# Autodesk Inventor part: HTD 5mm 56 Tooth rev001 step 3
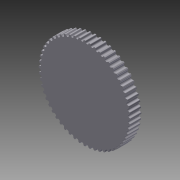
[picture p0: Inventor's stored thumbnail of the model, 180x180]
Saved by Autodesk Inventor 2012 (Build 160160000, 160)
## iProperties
Created: 2011-12
Part Number: HTD 5mm 56 Tooth rev001 step 3
Document SubType Name: Modeling
Designer: Alex
Density: 2.71 g/cm^3
Material: Aluminum-6061
Author: Alex
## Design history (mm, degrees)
sketch "Sketch2"
  geometry: C1 r 43.993 at (0, 0); 1 further point
  constraints: 1 centre point, 1 coincident
  dimensions: "d197" = 87.9856 diameter of C1
extrude "Extrusion1" new body sketch "Sketch2" distance "d198" = 10.5664; taper "d199" = 0 deg
sketch "Sketch1"
  geometry: L1 (0, 0)-(0, 28.7); L2 (-28.232, 0)-(27.326, 0); L3 (1.426, 25.389)-(0, 0); L4 (-1.426, 25.389)-(0, 0); L5 (2.201, 41.903)-(2.505, 41.886); L6 (0.897, 43.637)-(1.14, 42.758); L7 (3.994, 43.463)-(3.655, 42.617); L8 (-43.954, 44.031)-(44.031, 43.954); L9 (44.031, 43.954)-(43.954, -44.031); L10 (43.954, -44.031)-(-44.031, -43.954); L11 (-44.031, -43.954)-(-43.954, 44.031); L12 (-0.897, 43.637)-(-1.14, 42.758); L13 (-2.505, 41.886)-(-2.201, 41.903); L14 (-3.994, 43.463)-(-3.655, 42.617); L15 (-5.777, 43.262)-(-5.92, 42.362); L16 (-7.179, 41.342)-(-6.878, 41.393); L17 (-8.836, 42.742)-(-8.403, 41.94); L18 (-10.585, 42.343)-(-10.626, 41.433); L19 (-11.763, 40.279)-(-11.47, 40.363); L20 (-13.566, 41.484)-(-13.046, 40.735); L21 (-15.259, 40.892)-(-15.198, 39.982); L22 (-16.199, 38.708)-(-15.917, 38.825); L23 (-18.125, 39.705)-(-17.525, 39.019); L24 (-19.741, 38.926)-(-19.579, 38.029); L25 (-20.431, 36.651)-(-20.164, 36.799); L26 (-22.457, 37.426)-(-21.783, 36.811); L27 (-23.976, 36.471)-(-23.714, 35.598); L28 (-24.406, 34.133)-(-24.157, 34.31); L29 (-26.506, 34.676)-(-25.768, 34.141); L30 (-27.908, 33.557)-(-27.551, 32.719); L31 (-28.074, 31.186)-(-27.847, 31.389); L32 (-30.222, 31.49)-(-29.429, 31.041); L33 (-31.49, 30.222)-(-31.041, 29.429); L34 (-31.389, 27.847)-(-31.186, 28.074); L35 (-33.557, 27.908)-(-32.719, 27.551); L36 (-34.676, 26.506)-(-34.141, 25.768); L37 (-34.31, 24.157)-(-34.133, 24.406); L38 (-36.471, 23.976)-(-35.598, 23.714); L39 (-37.426, 22.457)-(-36.811, 21.783); L40 (-36.799, 20.164)-(-36.651, 20.431); L41 (-38.926, 19.741)-(-38.029, 19.579); L42 (-39.705, 18.125)-(-39.019, 17.525); L43 (-38.825, 15.917)-(-38.708, 16.199); L44 (-40.892, 15.259)-(-39.982, 15.198); L45 (-41.484, 13.566)-(-40.735, 13.046); L46 (-40.363, 11.47)-(-40.279, 11.763); L47 (-42.343, 10.585)-(-41.433, 10.626); L48 (-42.742, 8.836)-(-41.94, 8.403); L49 (-41.393, 6.878)-(-41.342, 7.179); L50 (-43.262, 5.777)-(-42.362, 5.92); L51 (-43.463, 3.994)-(-42.617, 3.655); L52 (-41.903, 2.201)-(-41.886, 2.505); L53 (-43.637, 0.897)-(-42.758, 1.14); L54 (-43.637, -0.897)-(-42.758, -1.14); L55 (-41.886, -2.505)-(-41.903, -2.201); L56 (-43.463, -3.994)-(-42.617, -3.655); L57 (-43.262, -5.777)-(-42.362, -5.92); L58 (-41.342, -7.179)-(-41.393, -6.878); L59 (-42.742, -8.836)-(-41.94, -8.403); L60 (-42.343, -10.585)-(-41.433, -10.626); L61 (-40.279, -11.763)-(-40.363, -11.47); L62 (-41.484, -13.566)-(-40.735, -13.046); L63 (-40.892, -15.259)-(-39.982, -15.198); L64 (-38.708, -16.199)-(-38.825, -15.917)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; A1 r 0.483 centre (4.442, 43.283) between (4.492, 43.763) and (3.994, 43.463); A2 r 0.483 centre (0.432, 43.508) between (0.897, 43.637) and (0.437, 43.991); A3 r 1.168 centre (2.266, 43.07) between (1.14, 42.758) and (2.201, 41.903); A4 r 1.168 centre (2.57, 43.053) between (2.505, 41.886) and (3.655, 42.617); A5 r 43.993 centre (0, 0) between (4.492, 43.763) and (0.437, 43.991); A6 r 43.993 centre (0, 0) between (-0.437, 43.991) and (-4.492, 43.763); A7 r 0.483 centre (-0.432, 43.508) between (-0.437, 43.991) and (-0.897, 43.637); A8 r 1.168 centre (-2.266, 43.07) between (-2.201, 41.903) and (-1.14, 42.758); A9 r 1.168 centre (-2.57, 43.053) between (-3.655, 42.617) and (-2.505, 41.886); A10 r 0.483 centre (-4.442, 43.283) between (-3.994, 43.463) and (-4.492, 43.763); A11 r 43.993 centre (0, 0) between (-5.359, 43.665) and (-9.363, 42.985); A12 r 0.483 centre (-5.3, 43.186) between (-5.359, 43.665) and (-5.777, 43.262); A13 r 1.168 centre (-7.074, 42.545) between (-6.878, 41.393) and (-5.92, 42.362); A14 r 1.168 centre (-7.375, 42.494) between (-8.403, 41.94) and (-7.179, 41.342); A15 r 0.483 centre (-9.26, 42.513) between (-8.836, 42.742) and (-9.363, 42.985); A16 r 43.993 centre (0, 0) between (-10.214, 42.791) and (-14.117, 41.666); A17 r 0.483 centre (-10.102, 42.321) between (-10.214, 42.791) and (-10.585, 42.343); A18 r 1.168 centre (-11.793, 41.486) between (-11.47, 40.363) and (-10.626, 41.433); A19 r 1.168 centre (-12.086, 41.401) between (-13.046, 40.735) and (-11.763, 40.279); A20 r 0.483 centre (-13.962, 41.209) between (-13.566, 41.484) and (-14.117, 41.666); A21 r 43.993 centre (0, 0) between (-14.941, 41.378) and (-18.693, 39.824); A22 r 0.483 centre (-14.777, 40.924) between (-14.941, 41.378) and (-15.259, 40.892); A23 r 1.168 centre (-16.364, 39.905) between (-15.917, 38.825) and (-15.198, 39.982); A24 r 1.168 centre (-16.646, 39.788) between (-17.525, 39.019) and (-16.199, 38.708); A25 r 0.483 centre (-18.488, 39.387) between (-18.125, 39.705) and (-18.693, 39.824); A26 r 43.993 centre (0, 0) between (-19.48, 39.445) and (-23.035, 37.48); A27 r 0.483 centre (-19.266, 39.012) between (-19.48, 39.445) and (-19.741, 38.926); A28 r 1.168 centre (-20.729, 37.821) between (-20.164, 36.799) and (-19.579, 38.029); A29 r 1.168 centre (-20.996, 37.674) between (-21.783, 36.811) and (-20.431, 36.651); A30 r 0.483 centre (-22.782, 37.069) between (-22.457, 37.426) and (-23.035, 37.48); A31 r 43.993 centre (0, 0) between (-23.774, 37.016) and (-27.086, 34.665); A32 r 0.483 centre (-23.513, 36.61) between (-23.774, 37.016) and (-23.976, 36.471); A33 r 1.168 centre (-24.833, 35.263) between (-24.157, 34.31) and (-23.714, 35.598); A34 r 1.168 centre (-25.082, 35.086) between (-25.768, 34.141) and (-24.406, 34.133); A35 r 0.483 centre (-26.789, 34.285) between (-26.506, 34.676) and (-27.086, 34.665); A36 r 43.993 centre (0, 0) between (-27.769, 34.121) and (-30.797, 31.415); A37 r 0.483 centre (-27.464, 33.747) between (-27.769, 34.121) and (-27.908, 33.557); A38 r 1.168 centre (-28.625, 32.261) between (-27.847, 31.389) and (-27.551, 32.719); A39 r 1.168 centre (-28.853, 32.057) between (-29.429, 31.041) and (-28.074, 31.186); A40 r 0.483 centre (-30.46, 31.07) between (-30.222, 31.49) and (-30.797, 31.415); A41 r 43.993 centre (0, 0) between (-31.415, 30.797) and (-34.121, 27.769); A42 r 0.483 centre (-31.07, 30.46) between (-31.415, 30.797) and (-31.49, 30.222); A43 r 1.168 centre (-32.057, 28.853) between (-31.186, 28.074) and (-31.041, 29.429); A44 r 1.168 centre (-32.261, 28.625) between (-32.719, 27.551) and (-31.389, 27.847); A45 r 0.483 centre (-33.747, 27.464) between (-33.557, 27.908) and (-34.121, 27.769); A46 r 43.993 centre (0, 0) between (-34.665, 27.086) and (-37.016, 23.774); A47 r 0.483 centre (-34.285, 26.789) between (-34.665, 27.086) and (-34.676, 26.506); A48 r 1.168 centre (-35.086, 25.082) between (-34.133, 24.406) and (-34.141, 25.768); A49 r 1.168 centre (-35.263, 24.833) between (-35.598, 23.714) and (-34.31, 24.157); A50 r 0.483 centre (-36.61, 23.513) between (-36.471, 23.976) and (-37.016, 23.774); A51 r 43.993 centre (0, 0) between (-37.48, 23.035) and (-39.445, 19.48); A52 r 0.483 centre (-37.069, 22.782) between (-37.48, 23.035) and (-37.426, 22.457); A53 r 1.168 centre (-37.674, 20.996) between (-36.651, 20.431) and (-36.811, 21.783); A54 r 1.168 centre (-37.821, 20.729) between (-38.029, 19.579) and (-36.799, 20.164); A55 r 0.483 centre (-39.012, 19.266) between (-38.926, 19.741) and (-39.445, 19.48); A56 r 43.993 centre (0, 0) between (-39.824, 18.693) and (-41.378, 14.941); A57 r 0.483 centre (-39.387, 18.488) between (-39.824, 18.693) and (-39.705, 18.125); A58 r 1.168 centre (-39.788, 16.646) between (-38.708, 16.199) and (-39.019, 17.525); A59 r 1.168 centre (-39.905, 16.364) between (-39.982, 15.198) and (-38.825, 15.917); A60 r 0.483 centre (-40.924, 14.777) between (-40.892, 15.259) and (-41.378, 14.941); A61 r 43.993 centre (0, 0) between (-41.666, 14.117) and (-42.791, 10.214); A62 r 0.483 centre (-41.209, 13.962) between (-41.666, 14.117) and (-41.484, 13.566); A63 r 1.168 centre (-41.401, 12.086) between (-40.279, 11.763) and (-40.735, 13.046); A64 r 1.168 centre (-41.486, 11.793) between (-41.433, 10.626) and (-40.363, 11.47)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; 3 further points; 1 other entity
  constraints: 560 point on circle, 344 end point, 280 centre point, 6 symmetric about line, 3 tangent, 2 perpendicular, 1 coincident, 1 point on line, 1 vertical, 1179 other
  dimensions: "d27" = 62.27085 dimension on L3 L1; "d66" = 0.4318 distance from line of A2.centre L1; "d82" = 0.1524 distance from line of L3 A3.centre; "d97" = 43.9928 distance from line of point (0, 0) L11; "d98" = 43.9928 distance from line of point (0, 0) L8; "d99" = 89.95 deg angle of L11 L2; "d101" = 87.9856 distance between parallel lines of L9 L11; "d140" = 360 deg dimension on point (0, 0) A1.start (derived)
extrude "Extrusion2" cut sketch "Sketch1" stored distance "d200" = 0; taper "d201" = 0 deg
body "Solid1"
node "Image2"
other parameters: "d0" = 87.9856, "d4" = 0.9652, "d27" = 62.27085, "d46" = 2.032, "d47" = 2.3368, "d66" = 0.4318, "d82" = 0.1524, "d97" = 43.9928, "d98" = 43.9928, "d99" = 15.69924, "d101" = 87.9856, "d140" = 360 deg (derived)
